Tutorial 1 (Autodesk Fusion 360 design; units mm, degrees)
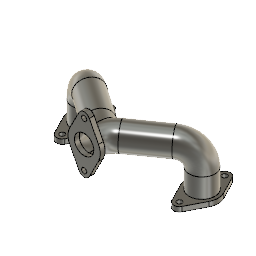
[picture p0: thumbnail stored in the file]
sketch "Sketch1" plane through (0, 0, 0) normal (0, 0, 1) x axis (1, 0, 0)
  line L1 (0, 0) -> (0, 0)
  line L2 (147.4474, -103.2438) -> (49.1491, -34.4146)
  line L3 (180, 0) -> (0, 0)
  arc A1 centre (101.5612, -168.7759) radius 80 clockwise from (147.4474, -103.2438) to (181.5613, -168.7759)
  arc A2 centre (49.1491, -34.4146) radius 60 between (0, 0) and (49.1491, -34.4146)
  point P1 (0, 0)
  point P2 (0, 0)
  point P6 (181.5613, -168.7759)
  point P7 (101.5612, -168.7759)
  point P3 (0, 0)
  point P4 (147.4474, -103.2438)
  coincident P1 P2
  horizontal L3
  tangent L2 A1
  horizontal P6 P7
  coincident P3 L1
  coincident P3 L2
  tangent L1 A2
  tangent L2 A2
  dimension "d1" distance P2 P3 = 120
  dimension "d2" angle L2 L3 = 35
  dimension "d3" distance P3 P4 = 180
  dimension "d4" radius A1 = 80
  dimension "d5" radius A2 = 60
pipe "Pipe1" SectionSize 80 SectionThickness 20
work_point "WorkPoint1"
work_plane "WorkPlane1" AlongDistance 181.561
mirror "Mirror1"
sketch "Sketch2" plane through (0, 0, 0) normal (0, 0, 1) x axis (1, 0, 0)
combine "Combine1"
shell "Shell1" innerThickness 10
sketch "Sketch3" plane through (0, 0, 0) normal (0, 0, 1) x axis (1, 0, 0)
  line L1 (-44.4697, 22.8571) -> (-16.0091, 78.2286)
  line L2 (-16.0091, -78.2286) -> (-44.4697, -22.8571)
  line L3 (44.4697, -22.8571) -> (16.0091, -78.2286)
  line L4 (16.0091, 78.2286) -> (44.4695, 22.8575)
  line L5 (0, 0) -> (0, 146.0781)
  line L6 (-87.5902, 0) -> (0, 0)
  arc A1 centre (0, 0) radius 50 clockwise from (-44.4697, -22.8571) to (-44.4697, 22.8571)
  arc A2 centre (0, 0) radius 50 clockwise from (44.4695, 22.8575) to (44.4697, -22.8571)
  arc A3 centre (0, -70) radius 18 clockwise from (16.0091, -78.2286) to (-16.0091, -78.2286)
  arc A4 centre (0, 70) radius 18 clockwise from (-16.0091, 78.2286) to (16.0091, 78.2286)
  circle C1 centre (0, 0) radius 30
  circle C2 centre (0, 70) radius 8
  circle C3 centre (0, -70) radius 8
  point P1 (0, 0)
  point P2 (0, 0)
  point P10 (44.4697, -22.8571)
  point P15 (0, 0)
  point P3 (0, 70)
  point P4 (0, -70)
  point P13 (0, 0)
  coincident P1 P2
  tangent L1 A1
  tangent L2 A3
  coincident P10 A1
  tangent L3 A1
  tangent L4 A4
  tangent L1 A4
  tangent L4 A1
  tangent L2 A1
  tangent L3 A3
  concentric A1 A2
  coincident P2 P15
  vertical L5
  horizontal L6
  symmetric P3 P4 L6
  vertical P3 P13
  equal A3 A4
  concentric A1 C1
  concentric A4 C2
  concentric A3 C3
  equal C2 C3
  dimension "d13" radius A2 = 50
  dimension "d14" radius A4 = 18
  dimension "d15" distance P3 P4 = 140
  dimension "d16" diameter C1 = 60
  dimension "d19" diameter C2 = 16
extrude "Extrude2" add sketch "Sketch3" profile of A2 A4 A3 L1 L2 L3 L4 C1 C2 C3 against normal blind 15
mirror "Mirror2"
sketch "Sketch4" plane through (0, -168.7759, 0) normal (0, -1, 0) x axis (1, 0, 0)
  line L1 (181.5613, 120) -> (181.5613, 254.3077)
  line L2 (265.8244, 120) -> (181.5613, 120)
  line L3 (137.0911, 142.8571) -> (165.5517, 198.2286)
  line L4 (165.5517, 41.7714) -> (137.0911, 97.1429)
  line L5 (226.0304, 97.1429) -> (197.5698, 41.7714)
  line L6 (197.5698, 198.2286) -> (226.0303, 142.8573)
  arc A1 centre (181.5607, 120) radius 30 clockwise from (181.5613, 150) to (181.5613, 90)
  arc A2 centre (181.5607, 120) radius 30 clockwise from (181.5613, 90) to (181.5613, 150)
  arc A3 centre (181.5613, 120) radius 40 clockwise from (181.561, 160) to (181.561, 80)
  arc A4 centre (181.5607, 120) radius 40 clockwise from (181.561, 80) to (181.561, 160)
  arc A5 centre (181.5607, 190) radius 18 clockwise from (165.5517, 198.2286) to (197.5698, 198.2286)
  arc A6 centre (181.5607, 120) radius 50 clockwise from (137.0911, 97.1429) to (137.0911, 142.8571)
  arc A7 centre (181.5607, 120) radius 50 clockwise from (226.0303, 142.8573) to (226.0304, 97.1429)
  arc A8 centre (181.5607, 50) radius 18 clockwise from (197.5698, 41.7714) to (165.5517, 41.7714)
  circle C1 centre (181.5607, 190) radius 8
  circle C2 centre (181.5607, 50) radius 8
  circle C3 centre (181.5607, 120) radius 30
  point P7 (181.5613, 120)
  point P12 (181.5613, 120)
  point P19 (226.0304, 97.1429)
  point P9 (181.5607, 190)
  point P10 (181.5607, 50)
  point P8 (181.5607, 120)
  concentric A1 A6
  coincident P7 P12
  vertical L1
  perpendicular L1 L2
  tangent L3 A6
  tangent L4 A8
  coincident P19 A6
  tangent L5 A6
  tangent L6 A5
  tangent L3 A5
  tangent L6 A6
  tangent L4 A6
  tangent L5 A8
  equal A5 A8
  symmetric P9 P10 L2
  concentric A6 A7
  vertical P8 P9
  concentric A5 C1
  concentric A8 C2
  equal C1 C2
  concentric A6 C3
  dimension "d23" radius A7 = 50
  dimension "d24" radius A5 = 18
  dimension "d25" distance P9 P10 = 140
  dimension "d26" diameter C1 = 16
  dimension "d27" diameter C3 = 60
extrude "Extrude3" add sketch "Sketch4" profile of A1 A2 A3 A4 A7 A5 A8 L3 L4 L5 L6 C1 C2 C3 along normal blind 15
